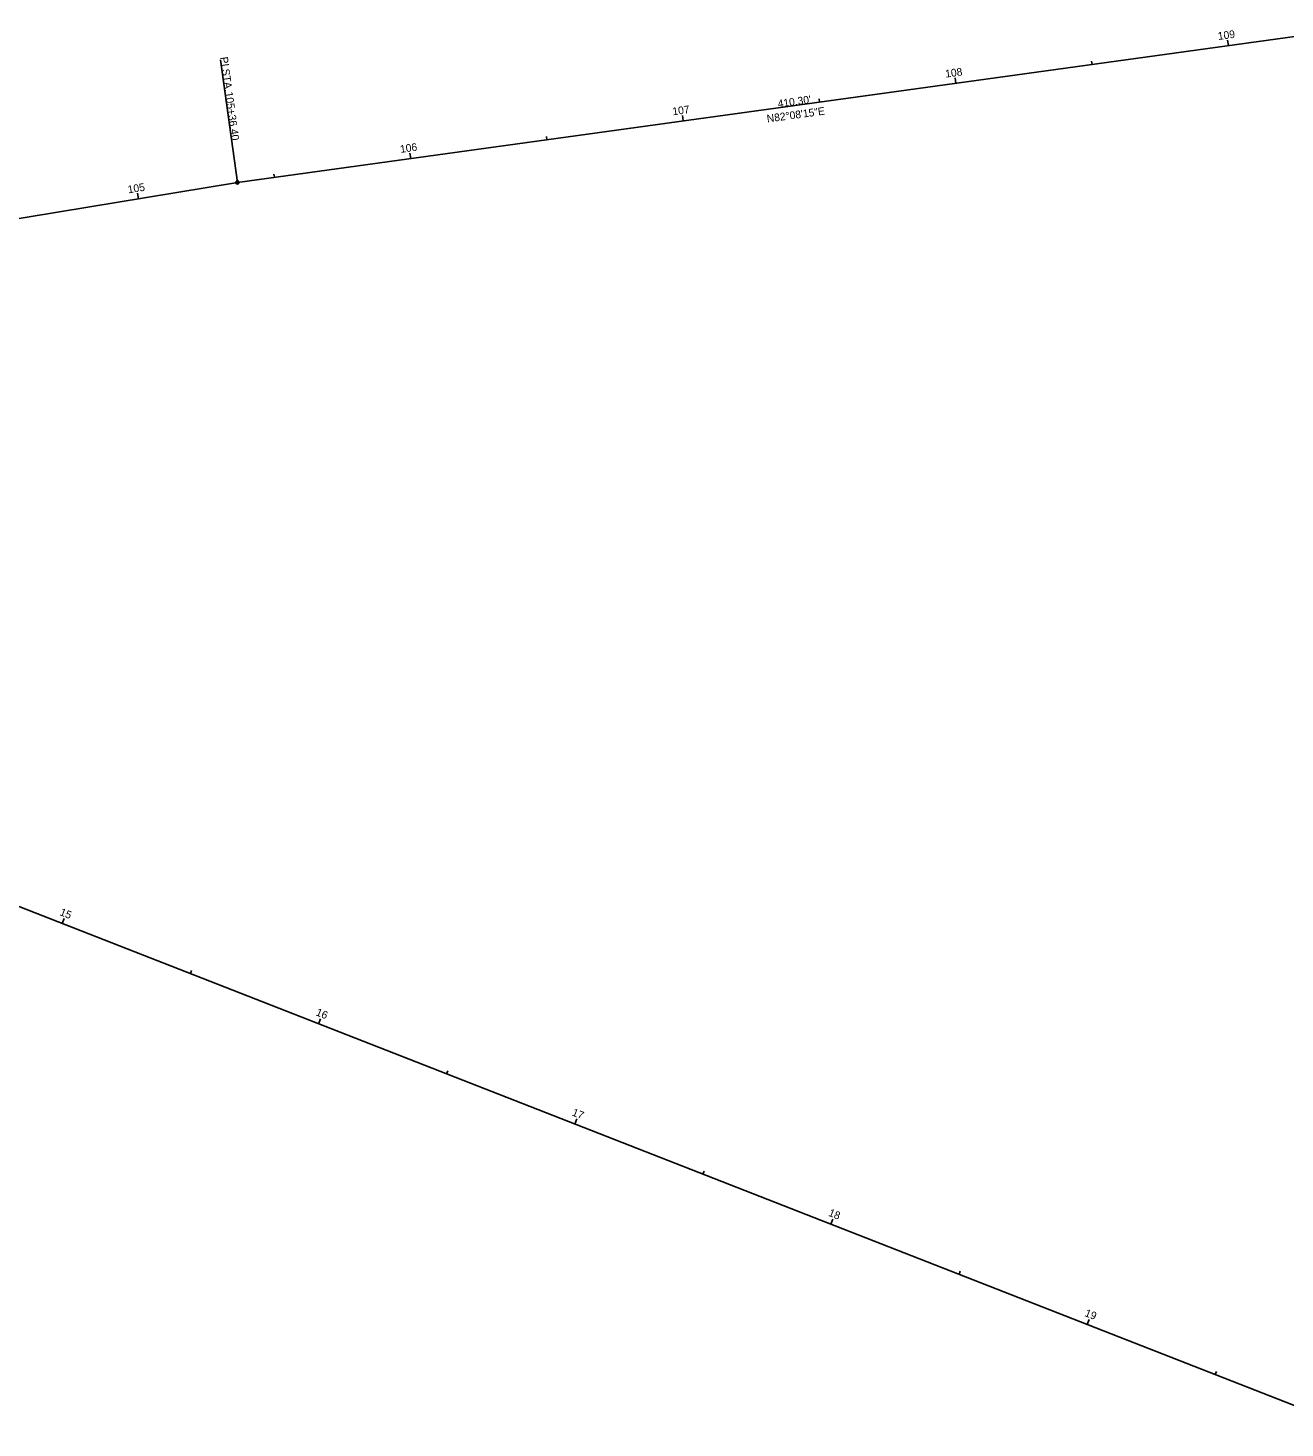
# Model space of a CAD drawing. Extents: x 1462082 to 1464344, y 432818 to 434093.
# Drawn here: x 1462543 to 1462999, y 433327 to 433836 of the extents above; entities that cross this region are included whole.
import ezdxf

# ---------------------------------------------------------------- set-up
doc = ezdxf.new("R2010")
doc.units = 0
for name, color, linetype in [('GE_P_Alignment', 7, 'Continuous'), ('GE_P_Alignment_100_Bearings', 7, 'Continuous'), ('GE_P_Alignment_100_Cardinal_Points', 7, 'Continuous'), ('GE_P_Alignment_100_Distances', 7, 'Continuous'), ('GE_P_Alignment_100_Stations', 7, 'Continuous')]:
    doc.layers.add(name, color=color, linetype=linetype)

msp = doc.modelspace()

# ---------------------------------------------------------------- linework, layer by layer
at = {"layer": 'GE_P_Alignment'}
for p, q in [((1462618.63, 433779.96), (1463025.07, 433836.09)), ((1462089.36, 433692.74), (1462618.63, 433779.96)), ((1462089.36, 433692.74), (1464324.41, 432818.38))]:
    msp.add_line(p, q, dxfattribs=at)
at = {"layer": 'GE_P_Alignment_100_Cardinal_Points'}
msp.add_line((1462618.63, 433779.96), (1462612.47, 433824.54), dxfattribs=at)
msp.add_circle((1462618.63, 433779.96), 0.6, dxfattribs=at)
at = {"layer": 'GE_P_Alignment_100_Stations'}
for p, q in [((1462978.81, 433829.7), (1462978.53, 433831.68)), ((1462929.28, 433822.86), (1462929.11, 433824.05)), ((1462879.75, 433816.02), (1462879.47, 433818)), ((1462830.22, 433809.18), (1462830.05, 433810.37)), ((1462780.69, 433802.34), (1462780.41, 433804.32)), ((1462731.16, 433795.5), (1462730.99, 433796.69)), ((1462681.63, 433788.66), (1462681.35, 433790.64)), ((1462632.1, 433781.82), (1462631.93, 433783.01)), ((1462582.71, 433774.04), (1462582.38, 433776.01)), ((1462555, 433510.58), (1462555.73, 433512.44)), ((1462601.56, 433492.36), (1462602, 433493.48)), ((1462648.13, 433474.14), (1462648.86, 433476.01)), ((1462694.69, 433455.93), (1462695.13, 433457.05)), ((1462741.26, 433437.71), (1462741.98, 433439.58)), ((1462787.82, 433419.5), (1462788.26, 433420.61)), ((1462834.38, 433401.28), (1462835.11, 433403.14)), ((1462880.95, 433383.07), (1462881.38, 433384.18)), ((1462927.51, 433364.85), (1462928.24, 433366.71)), ((1462974.07, 433346.63), (1462974.51, 433347.75))]:
    msp.add_line(p, q, dxfattribs=at)

# ---------------------------------------------------------------- texts
at = {"layer": 'GE_P_Alignment_100_Bearings'}
msp.add_text('N82°08\'15"E', height=2.8, rotation=7.8626, dxfattribs=at).set_placement((1462811.25, 433801.72))
at = {"layer": 'GE_P_Alignment_100_Cardinal_Points'}
for s, p in [('PI', (1462612.39, 433825.43)), (' STA. ', (1462612.85, 433822.07)), ('105+36.40', (1462614.15, 433812.71))]:
    msp.add_text(s, height=2.8, rotation=277.8626, dxfattribs=at).set_placement(p)
at = {"layer": 'GE_P_Alignment_100_Distances'}
msp.add_text("410.30'", height=2.8, rotation=7.8626, dxfattribs=at).set_placement((1462815.22, 433807.15))
at = {"layer": 'GE_P_Alignment_100_Stations'}
for s, rotation, p in [('109', 7.8626, (1462975.18, 433831.72)), ('108', 7.8626, (1462876.1, 433818.04)), ('107', 7.8626, (1462776.96, 433804.35)), ('106', 7.8626, (1462677.96, 433790.68)), ('105', 9.3585, (1462579.04, 433775.97)), ('15', 338.6344, (1462553.87, 433513.7)), ('16', 338.6344, (1462646.95, 433477.29)), ('17', 338.6344, (1462740.03, 433440.88)), ('18', 338.6344, (1462833.23, 433404.42)), ('19', 338.6344, (1462926.37, 433367.98))]:
    msp.add_text(s, height=2.8, rotation=rotation, dxfattribs=at).set_placement(p)

doc.saveas('drawing.dxf')
